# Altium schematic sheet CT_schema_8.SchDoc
size 278 x 170 mm
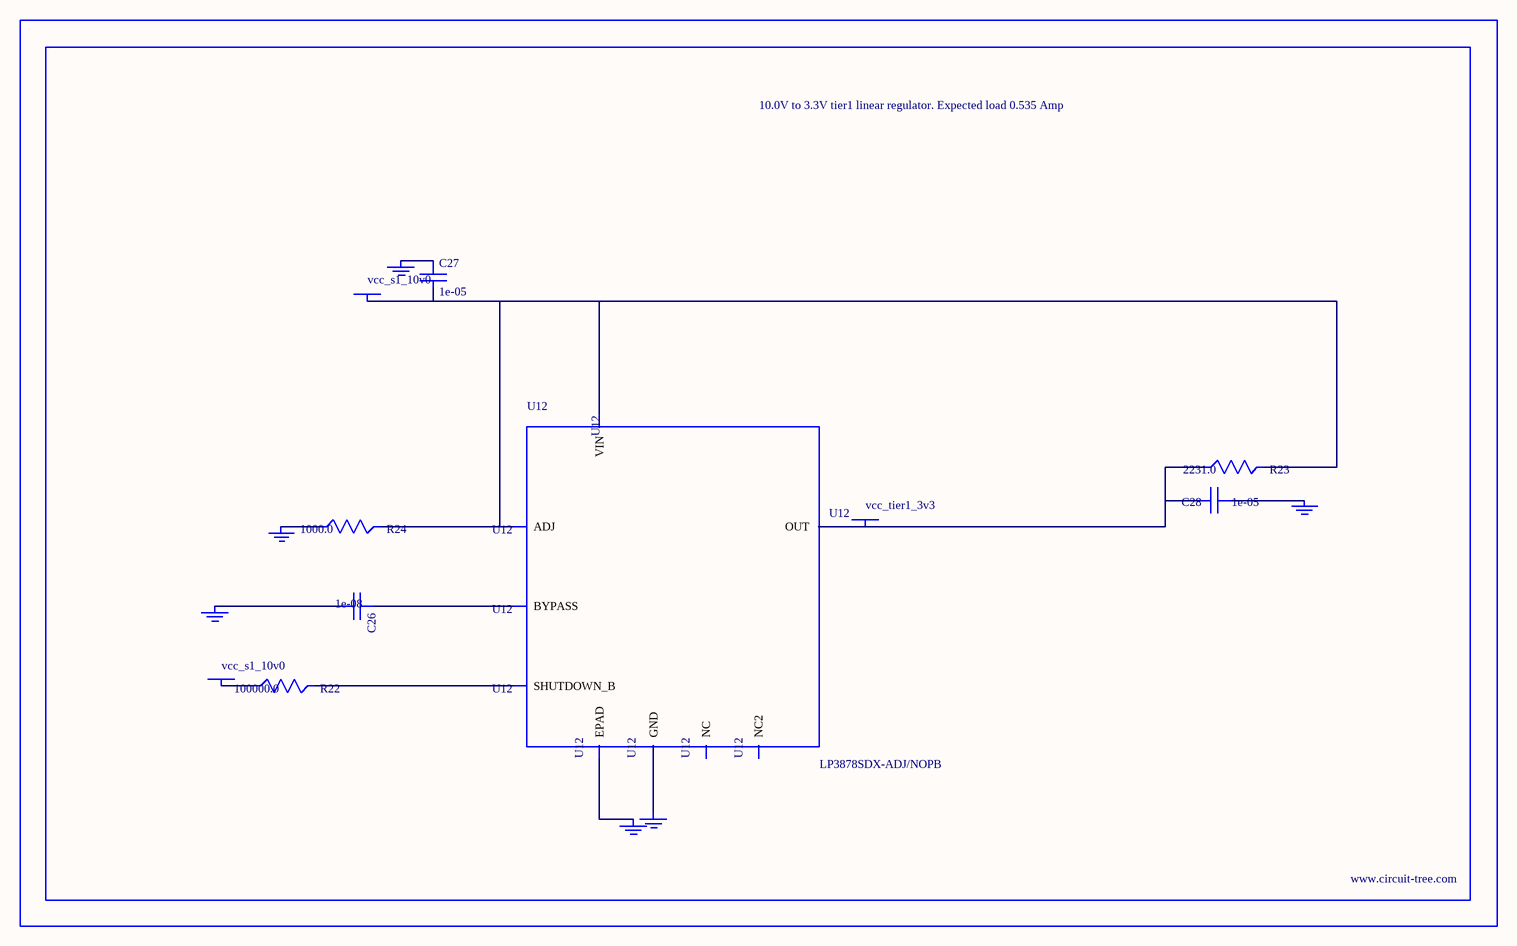
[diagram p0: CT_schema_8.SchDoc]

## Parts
BORDER7  (no value)
C26  1e-08  [C0402]
C27  1e-05  [C1206]
C28  1e-05  [C1210]
GND_INSTANCE_7_0  (no value)
GND_INSTANCE_7_1  (no value)
GND_INSTANCE_7_2  (no value)
GND_INSTANCE_7_3  (no value)
GND_INSTANCE_7_4  (no value)
GND_INSTANCE_7_5  (no value)
POWER_INSTANCE_7_0  vcc_s1_10v0
POWER_INSTANCE_7_1  vcc_s1_10v0
POWER_INSTANCE_7_2  vcc_tier1_3v3
R22  100000.0  [R0603]
R23  2231.0  [R0603]
R24  1000.0  [R0603]
U12  LP3878SDX-ADJ/NOPB  [WSON-8]

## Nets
NetC26_1: C26.1 U12.1(BYPASS)
NetC26_2: C26.2 GND_INSTANCE_7_0.0(GND)
NetC27_1: C27.1 GND_INSTANCE_7_1.0(GND)
NetC27_2: C27.2 POWER_INSTANCE_7_0.0(PWR) R23.2 R24.2 U12.4(VIN) U12.6(ADJ)
NetC28_1: C28.1 GND_INSTANCE_7_2.0(GND)
NetC28_2: C28.2 POWER_INSTANCE_7_2.0(PWR) R23.1 U12.5(OUT)
NetGND_INSTANCE_7_3_0: GND_INSTANCE_7_3.0(GND) R24.1
NetGND_INSTANCE_7_4_0: GND_INSTANCE_7_4.0(GND) U12.PAD(EPAD)
NetGND_INSTANCE_7_5_0: GND_INSTANCE_7_5.0(GND) U12.3(GND)
NetPOWER_INSTANCE_7_1_0: POWER_INSTANCE_7_1.0(PWR) R22.1
NetR22_2: R22.2 U12.8(SHUTDOWN_B)

Not connected (* = marked no-connect by the designer): U12 2(NC) 7(NC2)

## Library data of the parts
BORDER7 = BORDER_PAGE7
C26 = C0402C103K3RAC
C27 = C1206C106K3RACTU
C28 = GRM32DR61E106MA12L
GND_INSTANCE_7_0-GND_INSTANCE_7_5 = GND
POWER_INSTANCE_7_0-POWER_INSTANCE_7_2 = PWR
R22 = RC0603JR-07100KL
R23 = R23
R24 = RC0603JR-071KL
